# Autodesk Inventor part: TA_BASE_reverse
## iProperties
Created: 2006-11
Part Number: TA_BASE_reverse
Document SubType Name: Modeling
Designer: Lab User
Author: Lab User
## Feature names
1. Extrusion1
2. Hole1
3. Extrusion2
4. Hole2
5. Hole3
6. Hole4
7. Hole5
8. Hole6
9. Hole7
10. Hole8
11. Extrusion3
12. Hole9
13. Hole10
14. Extrusion4
15. Fillet1
